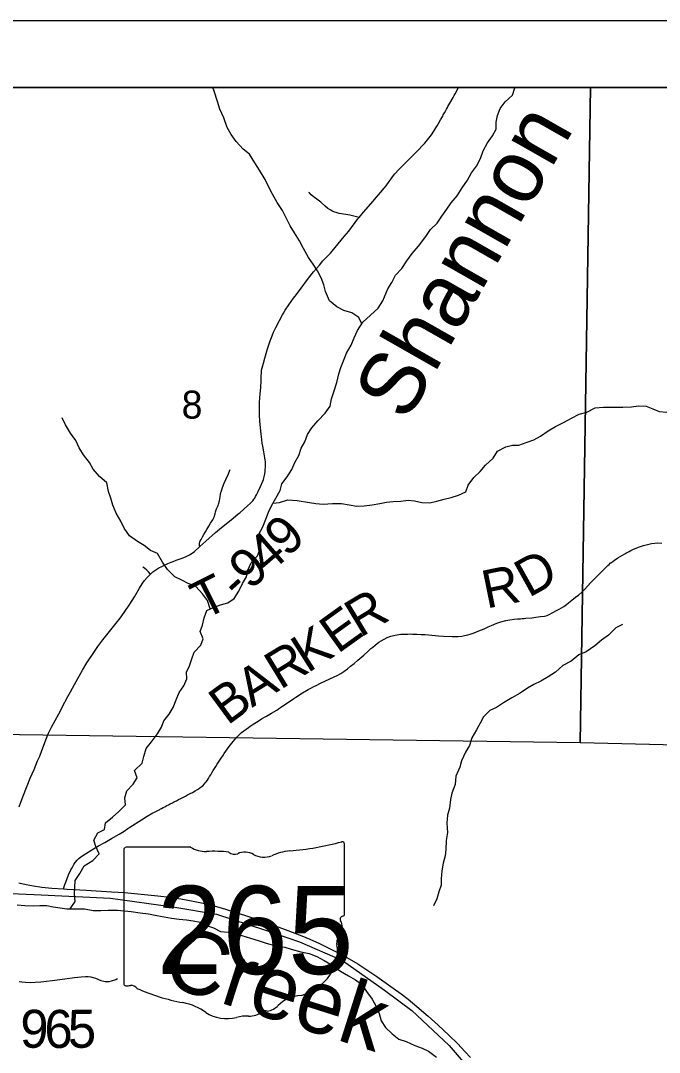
# Model space of a CAD drawing. Extents: x 0 to 34, y -8.9 to 22.
# Drawn here: x 26.944 to 27.898, y 12.462 to 14.004 of the extents above; entities that cross this region are included whole.
import ezdxf

# ---------------------------------------------------------------- set-up
doc = ezdxf.new("R2010")
doc.units = 0
for name, color, linetype in [('GM_X_Corporation', 7, 'Continuous'), ('GM_X_Minor_River', 7, 'Continuous'), ('GM_X_Minor_River_Text', 7, 'Continuous'), ('GM_X_Rail_Line', 7, 'Continuous'), ('GM_X_Section_Text', 7, 'Continuous'), ('GM_X_State_Location', 7, 'Continuous'), ('GM_X_State_Route', 7, 'Continuous'), ('GM_X_State_Shield', 7, 'Continuous'), ('GM_X_Township_Road', 7, 'Continuous'), ('GM_X_Township_Road_Text', 7, 'Continuous'), ('SH_Data', 7, 'Continuous')]:
    doc.layers.add(name, color=color, linetype=linetype)

msp = doc.modelspace()

# ---------------------------------------------------------------- linework, layer by layer
at = {"layer": 'GM_X_Corporation'}
for points in [[(28.8143, 13.904), (23.7167, 13.904), (23.7167, 11.9654), (24.1849, 11.9621), (24.2054, 11.9625), (24.3163, 11.9608), (25.0773, 11.948), (25.1035, 11.9505), (25.7218, 11.9377), (25.7578, 11.9372), (26.2139, 11.9314), (27.1396, 11.9157), (27.9423, 11.8981), (28.2591, 11.8967), (28.3241, 11.8942), (28.4085, 11.8914), (28.4711, 11.8911), (28.692, 11.888), (28.7762, 11.8872), (28.7779, 11.9899), (28.7786, 12.0342), (28.7787, 12.0377), (28.8049, 13.053), (28.8122, 13.7561)], [(28.8143, 13.904), (23.7167, 13.904), (23.7167, 11.9654), (24.1849, 11.9621), (24.2054, 11.9625), (24.3163, 11.9608), (25.0773, 11.948), (25.1035, 11.9505), (25.7218, 11.9377), (25.7578, 11.9372), (26.2139, 11.9314), (27.1396, 11.9157), (27.9423, 11.8981), (28.2591, 11.8967), (28.3241, 11.8942), (28.4085, 11.8914), (28.4711, 11.8911), (28.692, 11.888), (28.7762, 11.8872), (28.7779, 11.9899), (28.7786, 12.0342), (28.7787, 12.0377), (28.8049, 13.053), (28.8122, 13.7561)], [(27.795, 13.904), (26.7817, 13.904), (26.7664, 12.9392), (27.7795, 12.9249)], [(28.8115, 13.904), (27.795, 13.904), (27.7795, 12.9249), (28.7944, 12.9007), (28.7968, 13.0554)]]:
    msp.add_lwpolyline(points, close=True, dxfattribs=at)
at = {"layer": 'GM_X_Minor_River'}
for points in [[(27.4535, 13.5507), (27.449, 13.5604), (27.4387, 13.5671), (27.4266, 13.5708), (27.4159, 13.5763), (27.4053, 13.5853), (27.3991, 13.5992), (27.3967, 13.6091), (27.3928, 13.6197), (27.3874, 13.6302), (27.3805, 13.64), (27.374, 13.6501), (27.3663, 13.6633), (27.3601, 13.675), (27.3528, 13.6867), (27.3462, 13.6972), (27.3397, 13.71), (27.3347, 13.7202), (27.327, 13.7323), (27.32, 13.7447), (27.3143, 13.7552), (27.3092, 13.7666), (27.3004, 13.7805), (27.2938, 13.7914), (27.2858, 13.8042), (27.2762, 13.8121), (27.2659, 13.8233), (27.2582, 13.8338), (27.2524, 13.8444), (27.2474, 13.8587), (27.2412, 13.8719), (27.2377, 13.8833), (27.233, 13.8988), (27.2309, 13.904)], [(27.5732, 13.7118), (27.5806, 13.7221), (27.587, 13.7317), (27.5959, 13.742), (27.6034, 13.7542), (27.6116, 13.7657), (27.6175, 13.7764), (27.6246, 13.7864), (27.631, 13.7978), (27.6346, 13.8092), (27.6413, 13.8215), (27.6488, 13.8318), (27.6544, 13.8417), (27.6543, 13.852), (27.656, 13.8622), (27.6601, 13.8725), (27.6676, 13.8825), (27.6784, 13.8925), (27.6821, 13.9035), (27.6822, 13.904)], [(27.0178, 12.6764), (27.0252, 12.6873), (27.024, 12.6987), (27.0246, 12.7081), (27.0249, 12.7188), (27.032, 12.7291), (27.0387, 12.7406), (27.0515, 12.7483), (27.0608, 12.7583), (27.0562, 12.7692), (27.0531, 12.7791), (27.059, 12.7898), (27.0688, 12.7948), (27.0702, 12.8047), (27.0807, 12.8135), (27.0905, 12.8216), (27.1002, 12.8316), (27.0993, 12.8422), (27.1023, 12.8525), (27.112, 12.8625), (27.1176, 12.872), (27.1137, 12.883), (27.1253, 12.8938), (27.1279, 12.904), (27.1312, 12.9158), (27.1394, 12.9258), (27.148, 12.9377), (27.1543, 12.9476), (27.1576, 12.9571), (27.1655, 12.9675), (27.1714, 12.9774), (27.1762, 12.9885), (27.1806, 12.9995), (27.1877, 13.0095), (27.1922, 13.0201), (27.1917, 13.03), (27.1958, 13.0395), (27.1994, 13.0502), (27.2027, 13.0601), (27.2129, 13.0705), (27.2165, 13.08), (27.2119, 13.0906), (27.2152, 13.1005), (27.2177, 13.1115), (27.2218, 13.1222), (27.2327, 13.1272), (27.2425, 13.1308), (27.2531, 13.1339), (27.2629, 13.1401), (27.2696, 13.1512), (27.2751, 13.1626), (27.2811, 13.1726), (27.2833, 13.1825), (27.2881, 13.1935), (27.2978, 13.2039), (27.3022, 13.2157), (27.3029, 13.2256), (27.2998, 13.2365), (27.3057, 13.2472), (27.3101, 13.2587), (27.3138, 13.269), (27.3186, 13.2789), (27.3249, 13.2903), (27.3313, 13.3014), (27.3338, 13.3117), (27.3417, 13.322), (27.3487, 13.3331), (27.3532, 13.3434), (27.3591, 13.3537), (27.3628, 13.3648), (27.3684, 13.3743), (27.3724, 13.3854), (27.3788, 13.3953), (27.3877, 13.406), (27.3986, 13.4172), (27.4061, 13.4279), (27.4082, 13.4389), (27.4119, 13.4507), (27.4163, 13.4633), (27.4192, 13.4762), (27.4221, 13.4857), (27.4262, 13.4956), (27.4306, 13.5067), (27.4373, 13.5189), (27.4421, 13.5296), (27.447, 13.5407), (27.4552, 13.5533), (27.4664, 13.5637), (27.478, 13.5744), (27.4847, 13.5851), (27.4921, 13.603), (27.4981, 13.6126), (27.504, 13.6237), (27.513, 13.6333), (27.5208, 13.6447), (27.5287, 13.6558), (27.538, 13.6669), (27.5492, 13.6815), (27.5563, 13.6918), (27.5661, 13.7014), (27.5732, 13.7118)], [(27.3207, 13.2826), (27.3303, 13.2839), (27.3431, 13.2875), (27.3568, 13.2865), (27.3753, 13.2837), (27.3848, 13.282), (27.3958, 13.2813), (27.4098, 13.2823), (27.423, 13.282), (27.4344, 13.2803), (27.4462, 13.2782), (27.4568, 13.2787), (27.4688, 13.28), (27.4802, 13.282), (27.4904, 13.2844), (27.5002, 13.2853), (27.5119, 13.2858), (27.5225, 13.2871), (27.532, 13.286), (27.543, 13.2839), (27.5551, 13.2833), (27.5657, 13.2857), (27.5766, 13.2889), (27.5872, 13.2913), (27.5981, 13.2948), (27.609, 13.2995), (27.6124, 13.3094), (27.6206, 13.3209), (27.6303, 13.3301), (27.6385, 13.3397), (27.6498, 13.3501), (27.6561, 13.3604), (27.6685, 13.367), (27.6784, 13.3694), (27.6882, 13.3695), (27.6991, 13.3734), (27.7104, 13.3774), (27.7206, 13.3828), (27.7319, 13.3909), (27.7428, 13.3975), (27.7556, 13.4037), (27.7669, 13.4099), (27.7782, 13.4157), (27.7895, 13.4189), (27.8019, 13.4251), (27.8144, 13.4261), (27.8254, 13.4262), (27.8435, 13.426), (27.8564, 13.4269), (27.867, 13.4282), (27.8783, 13.4276), (27.8882, 13.4239), (27.8977, 13.4195), (27.9091, 13.4189)], [(27.2268, 13.1245), (27.2228, 13.137), (27.2155, 13.1471), (27.2052, 13.158), (27.1942, 13.1628), (27.1846, 13.1676), (27.174, 13.1724), (27.1633, 13.1837), (27.1556, 13.1946), (27.1479, 13.2074), (27.1377, 13.2118), (27.1281, 13.2196), (27.1182, 13.2256), (27.1064, 13.2338), (27.0983, 13.2451), (27.0933, 13.2556), (27.0864, 13.2677), (27.0814, 13.2798), (27.0782, 13.2903), (27.0747, 13.3002), (27.0723, 13.313), (27.0616, 13.3224), (27.0521, 13.3336), (27.0467, 13.3434), (27.0375, 13.3551), (27.0309, 13.3652), (27.0259, 13.3762), (27.0182, 13.3871), (27.0109, 13.3999), (27.0059, 13.4101)], [(27.843, 13.1013), (27.8328, 13.0963), (27.8223, 13.0855), (27.8114, 13.0778), (27.8017, 13.0693), (27.7889, 13.0605), (27.7776, 13.0558), (27.7663, 13.0465), (27.7539, 13.0399), (27.743, 13.0303), (27.7321, 13.0233), (27.7209, 13.0164), (27.7107, 13.0117), (27.7009, 13.0059), (27.69, 12.9985), (27.6776, 12.9919), (27.6652, 12.9842), (27.6546, 12.9773), (27.6449, 12.9726), (27.6351, 12.9634), (27.6303, 12.9538), (27.6247, 12.9439), (27.6176, 12.9317), (27.6143, 12.9202), (27.6084, 12.9107), (27.6025, 12.8977), (27.5999, 12.8882), (27.594, 12.8748), (27.593, 12.8619), (27.5882, 12.849), (27.586, 12.8395), (27.5846, 12.8269), (27.5817, 12.8163), (27.5807, 12.8041), (27.5816, 12.7905), (27.5794, 12.7783), (27.5792, 12.765), (27.5781, 12.7555), (27.5752, 12.7445), (27.5731, 12.7331), (27.5721, 12.7209), (27.5718, 12.7115), (27.5685, 12.7019), (27.5655, 12.6913), (27.5604, 12.6806)], [(26.9386, 12.682), (26.95, 12.6811), (26.9625, 12.6808), (26.9723, 12.6813), (26.9829, 12.6811), (26.9924, 12.6793), (27.0026, 12.6779), (27.0128, 12.6765), (27.0231, 12.6763), (27.0389, 12.6761), (27.0522, 12.674), (27.0636, 12.6737), (27.0745, 12.6742), (27.0882, 12.6744), (27.1086, 12.6724), (27.1223, 12.6703), (27.1348, 12.6689), (27.1473, 12.6664), (27.1693, 12.6621), (27.1806, 12.6607), (27.1916, 12.6597), (27.2015, 12.6583), (27.2117, 12.6562), (27.2216, 12.6514), (27.2318, 12.6477), (27.2421, 12.6425), (27.2535, 12.6415), (27.2633, 12.639), (27.274, 12.6365), (27.2869, 12.6325), (27.2986, 12.6288), (27.3104, 12.6248), (27.3248, 12.6212), (27.3385, 12.6191), (27.348, 12.6161), (27.3624, 12.6118), (27.3749, 12.6093), (27.3863, 12.6049), (27.3973, 12.5989), (27.4091, 12.5922), (27.4217, 12.5829), (27.4335, 12.5762), (27.4442, 12.5699), (27.4537, 12.5632), (27.4602, 12.5526), (27.469, 12.5414), (27.4748, 12.5301), (27.4795, 12.5199), (27.4822, 12.5089), (27.4888, 12.4987), (27.4987, 12.4894), (27.509, 12.4815), (27.5196, 12.4779), (27.5329, 12.472), (27.5436, 12.4679), (27.5531, 12.4635), (27.5649, 12.4545)]]:
    msp.add_lwpolyline(points, dxfattribs=at)
at = {"layer": 'GM_X_Rail_Line'}
msp.add_lwpolyline([(26.8928, 12.7005), (26.9639, 12.6979), (27.0777, 12.692), (27.1711, 12.6794), (27.2362, 12.6681), (27.3081, 12.645), (27.3605, 12.627), (27.4245, 12.5991), (27.4874, 12.5547), (27.528, 12.5242), (27.584, 12.472), (27.6341, 12.4131)], dxfattribs=at)
at = {"layer": 'GM_X_State_Route'}
msp.add_lwpolyline([(26.941, 12.7153), (26.9519, 12.7126), (26.9629, 12.7106), (26.9753, 12.7089), (26.9902, 12.7074), (27.0076, 12.7062), (27.0131, 12.7058), (27.0416, 12.704), (27.0795, 12.7018), (27.0987, 12.7005), (27.1488, 12.6959), (27.166, 12.6938), (27.1832, 12.6912), (27.2015, 12.6879), (27.2166, 12.6847), (27.2275, 12.6821), (27.2431, 12.6778), (27.2609, 12.6724), (27.281, 12.666), (27.3009, 12.6591), (27.3388, 12.6452), (27.3638, 12.6358), (27.3758, 12.6308), (27.39, 12.6245), (27.405, 12.6171), (27.4232, 12.6078), (27.4347, 12.6015), (27.4474, 12.5939), (27.461, 12.5852), (27.4759, 12.5751), (27.5002, 12.5579), (27.5123, 12.5491), (27.5226, 12.5411), (27.5359, 12.5301), (27.5524, 12.5159), (27.5677, 12.5022), (27.5835, 12.4873), (27.5968, 12.4743), (27.6075, 12.4631), (27.6159, 12.454)], dxfattribs=at)
at = {"layer": 'GM_X_State_Shield'}
for p, q in [((27.4275, 12.6686), (27.4275, 12.7732)), ((27.0979, 12.7648), (27.0979, 12.5647)), ((27.1977, 12.7683), (27.1011, 12.7683)), ((27.4274, 12.6686), (27.4275, 12.6686))]:
    msp.add_line(p, q, dxfattribs=at)
for centre, major_axis, start_param, end_param in [((27.3101, 13.0411), (0.3495, 0), 4.814394, 5.042369), ((27.4238, 12.7737), (0.00367, 0), 6.141152, 7.989035), ((27.1017, 12.7653), (0.00382, 0), 1.712693, 3.28349), ((27.2206, 12.7915), (0.037, 0), 4.042523, 4.731795), ((27.2329, 12.6559), (0.133, 0), 1.404758, 1.657858), ((27.2631, 12.7663), (0.0107, 0), 3.836095, 5.185415), ((27.2788, 12.7432), (0.0222, 0), 0.950623, 2.079405), ((27.3075, 12.7749), (0.0267, 0), 4.081561, 5.145723), ((27.3547, 12.7072), (0.0703, 0), 1.699011, 2.107814), ((27.4266, 12.6609), (0.00568, 0), 1.883978, 3.671073), ((27.4236, 12.6681), (0.00393, 0), 5.05454, 6.418171), ((27.3905, 12.6476), (0.0341, 0), 5.934695, 6.695948), ((27.4406, 12.6247), (0.0248, 0), 2.387724, 3.262537), ((27.3297, 12.6114), (0.0874, 0), 5.101752, 6.440018), ((27.1017, 12.5643), (0.00385, 0), 3.00124, 4.508301), ((27.1023, 12.5848), (0.0294, 0), 4.665946, 4.897461), ((27.1083, 12.5532), (0.0106, 0), 0.519207, 1.627899), ((27.2421, 12.733), (0.2524, 0), 4.195997, 4.488961), ((27.3665, 12.5085), (0.0479, 0), 1.647645, 2.488434), ((27.1669, 12.4748), (0.079, 0), 0.823519, 1.323587), ((27.3091, 12.5178), (0.00752, 0), 1.147584, 2.315152), ((27.3059, 12.5453), (0.0282, 0), 4.937069, 5.64225), ((27.2523, 12.5522), (0.0501, 0), 4.026481, 4.996735), ((27.2812, 12.483), (0.0412, 0), 1.495662, 1.94098), ((27.2849, 12.5372), (0.0267, 0), 4.691044, 5.507374)]:
    msp.add_ellipse(centre, major_axis=major_axis, ratio=0.8, start_param=start_param, end_param=end_param, dxfattribs=at)
at = {"layer": 'GM_X_Township_Road'}
for points in [[(27.4496, 13.7099), (27.4561, 13.7176), (27.4671, 13.7303), (27.4897, 13.7572), (27.4942, 13.7634), (27.4971, 13.7675), (27.4993, 13.7704), (27.5028, 13.7748), (27.509, 13.7817), (27.5138, 13.7865), (27.5218, 13.7944), (27.527, 13.7997), (27.5335, 13.8063), (27.5392, 13.812), (27.5433, 13.8163), (27.5476, 13.8209), (27.5516, 13.8256), (27.5576, 13.8335), (27.5611, 13.8386), (27.5642, 13.844), (27.5658, 13.8466), (27.568, 13.8503), (27.571, 13.8556), (27.5743, 13.8614), (27.5752, 13.863), (27.576, 13.8645), (27.5769, 13.866), (27.5788, 13.8696), (27.5799, 13.8716), (27.5813, 13.8743), (27.5822, 13.8759), (27.5849, 13.8807), (27.5897, 13.8892), (27.5912, 13.8919), (27.5927, 13.8946), (27.5978, 13.904)], [(27.4496, 13.7099), (27.4415, 13.7118), (27.4355, 13.7132), (27.4295, 13.7142), (27.4198, 13.7159), (27.4168, 13.7166), (27.4151, 13.717), (27.4133, 13.7176), (27.4116, 13.7182), (27.4099, 13.7189), (27.4061, 13.721), (27.4026, 13.7234), (27.3988, 13.7265), (27.3924, 13.7324), (27.388, 13.7358), (27.3806, 13.7413), (27.3778, 13.7437), (27.3752, 13.7464), (27.3744, 13.7473)], [(27.2112, 13.2177), (27.2157, 13.2217), (27.2204, 13.2257), (27.2346, 13.2387), (27.2407, 13.2439), (27.2611, 13.2601), (27.2687, 13.2665), (27.271, 13.2684), (27.2772, 13.2735), (27.2823, 13.278), (27.2877, 13.2831), (27.2906, 13.2864), (27.2922, 13.2885), (27.2935, 13.2904), (27.2948, 13.2927), (27.2963, 13.2953), (27.2986, 13.3003), (27.302, 13.3076), (27.3054, 13.3156), (27.3063, 13.3181), (27.307, 13.3203), (27.3075, 13.322), (27.3079, 13.3239), (27.3084, 13.3267), (27.3089, 13.3301), (27.3092, 13.333), (27.3093, 13.3362), (27.3094, 13.3409), (27.3094, 13.3433), (27.3093, 13.3451), (27.3091, 13.3468), (27.3085, 13.3504), (27.3068, 13.3592), (27.3053, 13.3677), (27.3046, 13.3724), (27.3035, 13.3822), (27.3031, 13.3853), (27.302, 13.3958), (27.3012, 13.4051), (27.3006, 13.4144), (27.3006, 13.433), (27.3009, 13.4399), (27.3015, 13.4462), (27.3019, 13.4504), (27.3023, 13.456), (27.3028, 13.4652), (27.3029, 13.4727), (27.3033, 13.4782), (27.3037, 13.4813), (27.3045, 13.4849), (27.3063, 13.4921), (27.3083, 13.4993), (27.3127, 13.5136), (27.3166, 13.5254), (27.3194, 13.5329), (27.3215, 13.5381), (27.3248, 13.5455), (27.3302, 13.556), (27.3348, 13.5641), (27.3364, 13.5667), (27.339, 13.571), (27.3444, 13.5793), (27.3512, 13.5889), (27.3556, 13.5948), (27.3626, 13.6043), (27.3724, 13.6171), (27.3812, 13.6283), (27.39, 13.6387), (27.3954, 13.6447), (27.4064, 13.6565), (27.4137, 13.6649), (27.4272, 13.6811), (27.4338, 13.6894), (27.4477, 13.7076), (27.4496, 13.7099)], [(27.2112, 13.2177), (27.211, 13.2195), (27.2109, 13.2203), (27.2109, 13.2211), (27.2109, 13.2219), (27.2109, 13.2228), (27.2111, 13.2236), (27.2114, 13.2246), (27.2116, 13.2254), (27.212, 13.2261), (27.2132, 13.2286), (27.2152, 13.2322), (27.2173, 13.2358), (27.2198, 13.24), (27.2217, 13.2432), (27.225, 13.2485), (27.2274, 13.2528), (27.2308, 13.258), (27.2317, 13.2597), (27.2325, 13.2612), (27.233, 13.2624), (27.2334, 13.2635), (27.2338, 13.2651), (27.2342, 13.2666), (27.2349, 13.2696), (27.2353, 13.271), (27.2359, 13.2727), (27.2365, 13.2742), (27.2378, 13.277), (27.2386, 13.279), (27.2393, 13.281), (27.2406, 13.2863), (27.2417, 13.2924), (27.2424, 13.296), (27.243, 13.2984), (27.2435, 13.2998), (27.2454, 13.3061), (27.2476, 13.3125), (27.2501, 13.3182), (27.2542, 13.3264), (27.2564, 13.3318), (27.2567, 13.3329)], [(27.0076, 12.7062), (27.0098, 12.7128), (27.011, 12.7162), (27.0153, 12.7272), (27.0187, 12.7345), (27.0204, 12.7378), (27.0232, 12.7427), (27.0252, 12.7457), (27.0281, 12.749), (27.0308, 12.7516), (27.0337, 12.7539), (27.0404, 12.7584), (27.0499, 12.7643), (27.0601, 12.7702), (27.0694, 12.7753), (27.0796, 12.7812), (27.0907, 12.788), (27.0981, 12.7925), (27.1038, 12.7962), (27.107, 12.7982), (27.124, 12.8093), (27.1329, 12.8149), (27.1414, 12.8197), (27.1435, 12.8209), (27.1515, 12.825), (27.1526, 12.8256), (27.1542, 12.8264), (27.1568, 12.8278), (27.1589, 12.8288), (27.162, 12.8305), (27.1647, 12.8318), (27.1673, 12.8332), (27.1705, 12.8349), (27.1737, 12.8365), (27.1764, 12.8379), (27.1796, 12.8396), (27.1828, 12.8412), (27.186, 12.8429), (27.1898, 12.8449), (27.193, 12.8466), (27.1969, 12.8485), (27.2002, 12.8502), (27.2046, 12.8525), (27.2077, 12.8545), (27.2108, 12.8565), (27.2133, 12.8584), (27.2157, 12.8603), (27.2183, 12.863), (27.2195, 12.8644), (27.221, 12.8663), (27.2227, 12.8688), (27.2241, 12.8709), (27.226, 12.874), (27.2277, 12.8766), (27.2295, 12.8798), (27.2315, 12.8829), (27.2334, 12.886), (27.2354, 12.8892), (27.2373, 12.8923), (27.2393, 12.8955), (27.2413, 12.8985), (27.2433, 12.9016), (27.2457, 12.9052), (27.2478, 12.9083), (27.2502, 12.9118), (27.2552, 12.9189), (27.261, 12.9262), (27.2666, 12.9329), (27.2705, 12.9369), (27.2737, 12.9398), (27.2807, 12.945), (27.2842, 12.9475), (27.2867, 12.9493), (27.2897, 12.9514), (27.2934, 12.9537), (27.296, 12.9555), (27.3002, 12.958), (27.3033, 12.9601), (27.3081, 12.9628), (27.3108, 12.9644), (27.3135, 12.9659), (27.3183, 12.9687), (27.3263, 12.9734), (27.3288, 12.9751), (27.3319, 12.9772), (27.3519, 12.9907), (27.355, 12.9927), (27.3649, 12.9991), (27.3734, 13.0041), (27.3761, 13.0056), (27.3782, 13.0068), (27.3815, 13.0085), (27.3851, 13.0103), (27.3919, 13.0136), (27.3992, 13.0171), (27.411, 13.0224), (27.4175, 13.0256), (27.4223, 13.0283), (27.4264, 13.031), (27.4318, 13.0351), (27.4367, 13.0388), (27.4421, 13.043), (27.4477, 13.0479), (27.4566, 13.0556), (27.4624, 13.0611), (27.4669, 13.0653), (27.4697, 13.0676), (27.4736, 13.0706), (27.4791, 13.0747), (27.4822, 13.0767), (27.487, 13.0796), (27.4915, 13.0817), (27.4967, 13.0837), (27.5033, 13.0853), (27.5119, 13.0867), (27.5187, 13.0871), (27.5224, 13.0871), (27.5255, 13.0872), (27.5292, 13.087), (27.536, 13.0869), (27.5422, 13.0866), (27.5483, 13.0862), (27.5533, 13.0857), (27.5678, 13.0844), (27.5757, 13.0839), (27.5884, 13.0834), (27.5969, 13.0834), (27.6029, 13.084), (27.6071, 13.0847), (27.6119, 13.0858), (27.6155, 13.0869), (27.6213, 13.089), (27.6282, 13.0916), (27.6362, 13.095), (27.6423, 13.0978), (27.6474, 13.1), (27.6554, 13.1032), (27.6613, 13.1052), (27.6685, 13.1071), (27.6746, 13.1083), (27.6813, 13.1092), (27.6862, 13.1096), (27.6905, 13.11), (27.693, 13.1102), (27.696, 13.1105), (27.6985, 13.1107), (27.7077, 13.1114), (27.7137, 13.1121), (27.7204, 13.1131), (27.7265, 13.114), (27.7303, 13.115), (27.7333, 13.1161), (27.7446, 13.122), (27.7484, 13.1241), (27.7516, 13.126), (27.7552, 13.1283), (27.7593, 13.1312), (27.768, 13.138), (27.7747, 13.1435), (27.777, 13.1453), (27.7825, 13.1501), (27.7865, 13.154), (27.7954, 13.1634), (27.8079, 13.1764), (27.8162, 13.1847), (27.8187, 13.1872), (27.8204, 13.1888), (27.8213, 13.1896), (27.823, 13.1912), (27.8248, 13.1928), (27.827, 13.1946), (27.8284, 13.1957), (27.8309, 13.1974), (27.8328, 13.1989), (27.8338, 13.1995), (27.8359, 13.2008), (27.8428, 13.2048), (27.8465, 13.207), (27.848, 13.2078), (27.8502, 13.209), (27.8528, 13.2105), (27.8555, 13.212), (27.8582, 13.2134), (27.8593, 13.2139), (27.8682, 13.2174), (27.8745, 13.2193), (27.8803, 13.2209), (27.8863, 13.2223), (27.8912, 13.223), (27.8955, 13.2233), (27.9017, 13.2231)], [(27.1378, 13.1767), (27.1414, 13.1798), (27.1458, 13.1832), (27.15, 13.1858), (27.1545, 13.188), (27.1634, 13.1923), (27.1685, 13.1945), (27.1714, 13.1957), (27.176, 13.1975), (27.1848, 13.2007), (27.1911, 13.2032), (27.1961, 13.2056), (27.1999, 13.2078), (27.2033, 13.2104), (27.2112, 13.2177)], [(27.1378, 13.1767), (27.1345, 13.1801), (27.1324, 13.1823), (27.1285, 13.1854), (27.126, 13.1872)], [(26.9413, 12.8288), (26.9439, 12.8358), (26.9478, 12.8462), (26.958, 12.8716), (26.9636, 12.8847), (26.969, 12.8973), (26.97, 12.8996), (26.9721, 12.9047), (26.9752, 12.9129), (26.9822, 12.9315), (26.9853, 12.9389), (26.9897, 12.9478), (27.0006, 12.968), (27.0095, 12.9851), (27.0142, 12.9938), (27.0182, 13.0008), (27.0242, 13.0117), (27.0359, 13.0329), (27.0427, 13.0441), (27.0531, 13.0596), (27.0591, 13.0682), (27.0664, 13.0782), (27.0764, 13.0909), (27.0922, 13.1109), (27.0985, 13.1193), (27.1068, 13.1317), (27.1136, 13.1428), (27.1212, 13.1556), (27.1252, 13.1619), (27.1288, 13.167), (27.1327, 13.1718), (27.1362, 13.1753), (27.1378, 13.1767)], [(26.9415, 12.5676), (26.9452, 12.567), (26.9508, 12.5665), (26.9577, 12.5663), (26.9651, 12.5664), (26.9738, 12.5671), (26.9905, 12.569), (27.0096, 12.5716), (27.0243, 12.5737), (27.0341, 12.5748), (27.0403, 12.5752), (27.0447, 12.575), (27.0483, 12.5746), (27.0502, 12.5742), (27.052, 12.5737), (27.0555, 12.5725), (27.0635, 12.5692), (27.0677, 12.5679), (27.0701, 12.5675), (27.0732, 12.5674), (27.0757, 12.5676), (27.0793, 12.5685), (27.0857, 12.5708), (27.0886, 12.572)]]:
    msp.add_lwpolyline(points, dxfattribs=at)
at = {"layer": 'SH_Data'}
for points in [[(23.6167, 14.004), (30.6167, 14.004), (30.6167, 7.004), (23.6167, 7.004)], [(23.7167, 13.904), (30.5167, 13.904), (30.5167, 7.104), (23.7167, 7.104)]]:
    msp.add_lwpolyline(points, close=True, dxfattribs=at)

# ---------------------------------------------------------------- texts
at = {"layer": 'GM_X_Minor_River_Text'}
for s, height, rotation, p in [('Shannon', 0.09468, 60.3336, (27.5201, 13.4021)), ('Creek', 0.09469, 342.3423, (27.1518, 12.5645))]:
    msp.add_text(s, height=height, rotation=rotation, dxfattribs=at).set_placement(p)
at = {"layer": 'GM_X_Section_Text'}
msp.add_text('8', height=0.0419, rotation=0, dxfattribs=at).set_placement((27.1842, 13.4091))
at = {"layer": 'GM_X_State_Location'}
for s in ['s', 'r']:
    msp.add_text(s, height=0.000189, dxfattribs=at).set_placement((27.259, 12.6515))
msp.add_text('265', height=0.000189, rotation=0, dxfattribs=at).set_placement((27.1921, 12.6377))
at = {"layer": 'GM_X_State_Shield'}
msp.add_text('265', height=0.13184, dxfattribs=at).set_placement((27.147, 12.5788))
at = {"layer": 'GM_X_Township_Road_Text'}
for s, rotation, p in [('9', 44.583, (27.3423, 13.2003)), ('4', 40.8033, (27.3128, 13.1746)), ('9', 40.6352, (27.2861, 13.1517)), ('D', 29.0913, (27.7028, 13.1407)), ('R', 11.5128, (27.6395, 13.1249)), ('T', 26.6225, (27.2172, 13.1076)), ('-', 42.371, (27.2692, 13.1363)), ('R', 31.1692, (27.451, 13.0809)), ('E', 35.6995, (27.4174, 13.0567)), ('K', 32.3828, (27.3722, 13.0279)), ('R', 31.3761, (27.3315, 13.0031)), ('A', 32.0733, (27.2893, 12.9766)), ('B', 36.368, (27.2526, 12.9496)), ('9', 358.3817, (26.9422, 12.4692)), ('6', 0.3457, (26.9793, 12.4682)), ('5', 0.4677, (27.0144, 12.4684))]:
    msp.add_text(s, height=0.0568, rotation=rotation, dxfattribs=at).set_placement(p)

doc.saveas('drawing.dxf')
